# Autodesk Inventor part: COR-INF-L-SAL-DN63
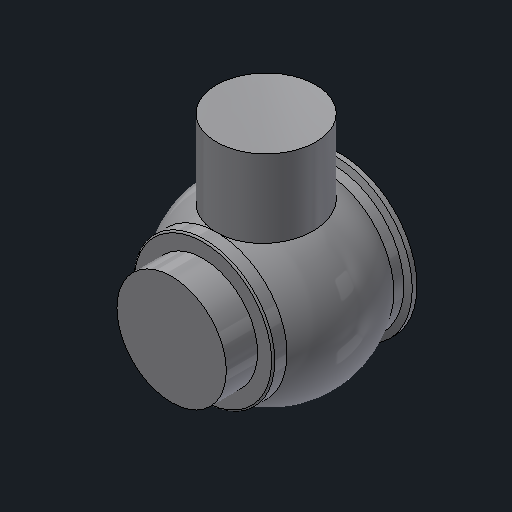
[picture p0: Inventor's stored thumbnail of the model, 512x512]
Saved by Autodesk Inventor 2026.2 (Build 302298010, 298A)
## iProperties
Created: 2026-03
Part Number: COR-INF-L-SAL-DN63
Material: Generico
Document SubType Name: Modeling
Designer: marz-m
Density: 1 g/cm^3
Appearance: Default
Author: marz-m
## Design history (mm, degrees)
feature "Solido1"
node "Solido2"
